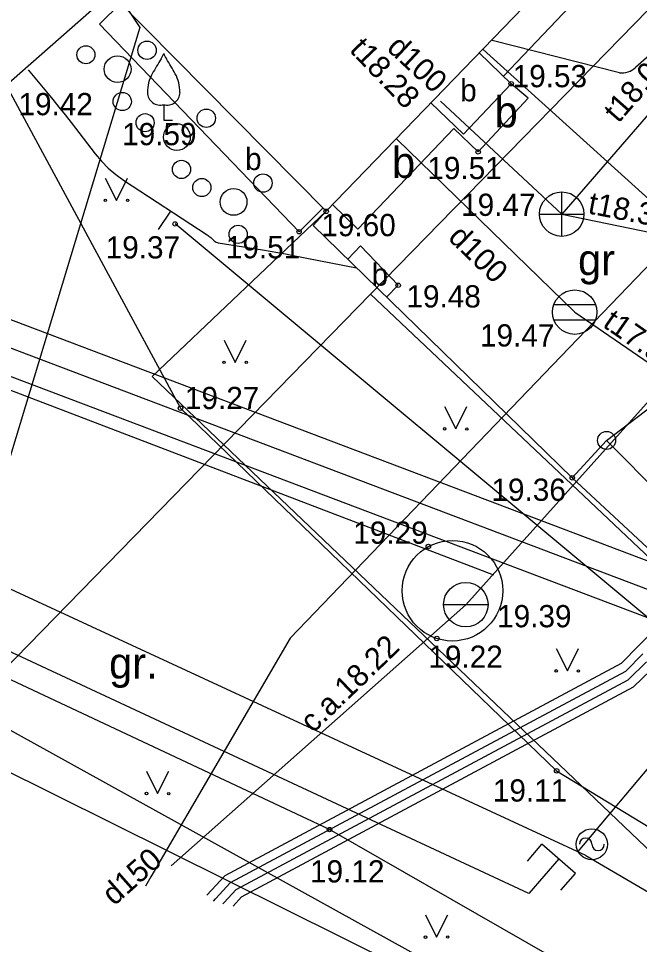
# Model space of a CAD drawing. Extents: x 532933 to 533143, y 328014 to 328163.
# Drawn here: x 532971.35 to 532985.32, y 328041.74 to 328062.57 of the extents above; entities that cross this region are included whole.
import ezdxf

# ---------------------------------------------------------------- set-up
doc = ezdxf.new("R2010")
doc.units = 0
for name, color, linetype in [('BUVE_BDET_####_####_#', 7, 'Continuous'), ('BUVE_BDET_####_TKST_#', 7, 'Continuous'), ('BUVE_EKAS_####_####_#', 7, 'Continuous'), ('CELI_CMAL_####_####_#', 7, 'Continuous'), ('CELI_CSEG_####_TKST_#', 7, 'Continuous'), ('ELEK_VADP_NEDR_####_#', 7, 'Continuous'), ('ELEK_VADP_VSPR_####_#', 7, 'Continuous'), ('ELEK_VADP_ZSPR_####_#', 7, 'Continuous'), ('GAZE_ELEM_####_####_#', 7, 'Continuous'), ('GAZE_VADP_ASP1_####_I', 7, 'Continuous'), ('GAZE_VADP_NEDR_####_#', 7, 'Continuous'), ('GAZE_VADP_ZSPD_####_#', 7, 'Continuous'), ('LKAN_ELEM_####_####_#', 7, 'Continuous'), ('LKAN_ELEM_PAST_TKST_#', 7, 'Continuous'), ('LKAN_VADP_PAST_####_#', 7, 'Continuous'), ('LKAN_VADP_PAST_TKST_#', 7, 'Continuous'), ('NORB_ELEM_####_####_#', 7, 'Continuous'), ('NORB_ZOGS_BARJ_####_#', 7, 'Continuous'), ('NORB_ZOGS_ZSTP_####_#', 7, 'Continuous'), ('RAMI_UZMR_####_####_#', 7, 'Continuous'), ('RELJ_AATZ_####_TKST_#', 7, 'Continuous'), ('RELJ_ELEM_####_####_#', 7, 'Continuous'), ('RELJ_HORZ_PAMT_####_#', 7, 'Continuous'), ('ROBZ_UZMR_####_####_#', 7, 'Continuous'), ('SAKT_VADP_KABE_####_#', 7, 'Continuous'), ('SAKT_VADV_PKAB_####_#', 7, 'Continuous'), ('SILT_VADP_UDEN_####_#', 7, 'Continuous'), ('SILT_VADP_UDEN_TKAM_#', 7, 'Continuous'), ('SKAN_ELEM_####_####_#', 7, 'Continuous'), ('SKAN_ELEM_PAST_TKST_#', 7, 'Continuous'), ('SKAN_VADP_PAST_####_#', 7, 'Continuous'), ('SKAN_VADP_PAST_TKST_#', 7, 'Continuous'), ('TERT_ELEM_####_####_#', 7, 'Continuous'), ('TERT_KRND_####_####_#', 7, 'Continuous'), ('UDTK_DETV_####_####_#', 7, 'Continuous'), ('UDTK_ELEM_####_####_#', 7, 'Continuous'), ('UDTK_ELEM_####_TKST_#', 7, 'Continuous'), ('UDTK_VADP_UDEN_####_#', 7, 'Continuous'), ('UDTK_VADP_UDEN_TKST_#', 7, 'Continuous')]:
    doc.layers.add(name, color=color, linetype=linetype)

msp = doc.modelspace()

# ---------------------------------------------------------------- linework, layer by layer
at = {"layer": 'BUVE_BDET_####_####_#'}
for p, q in [((532973.651, 328062.91), (532973.174, 328062.438)), ((532977.663, 328057.772), (532973.174, 328062.438)), ((532981.715, 328061.795), (532982.435, 328061.1)), ((532982.435, 328061.1), (532981.359, 328059.968)), ((532980.63, 328060.672), (532981.359, 328059.968)), ((532978.201, 328058.303), (532977.663, 328057.772)), ((532978.757, 328057.152), (532979.047, 328057.451)), ((532979.047, 328057.451), (532979.893, 328056.568)), ((532979.632, 328056.3), (532979.893, 328056.568))]:
    msp.add_line(p, q, dxfattribs=at)
msp.add_lwpolyline([(532973.427, 328063.138), (532969.826, 328059.969), (532963.605, 328066.425), (532962.603, 328070.346), (532963.994, 328070.869)], dxfattribs=at)
at = {"layer": 'BUVE_EKAS_####_####_#'}
for p, q in [((532991.271, 328071.691), (532978.273, 328058.231)), ((532978.273, 328058.231), (532973.38, 328063.184))]:
    msp.add_line(p, q, dxfattribs=at)
at = {"layer": 'CELI_CMAL_####_####_#'}
for p, q in [((532982.814, 328060.778), (532982.435, 328061.1)), ((532981.691, 328059.567), (532982.814, 328060.778)), ((532981.143, 328060.097), (532981.691, 328059.567)), ((532978.418, 328058.381), (532978.987, 328057.831))]:
    msp.add_line(p, q, dxfattribs=at)
for points in [[(532982.259, 328061.27), (532998.656, 328078.496)], [(533000, 328031.505), (532994.447, 328035.097), (532978.349, 328044.324), (532965.504, 328050.351), (532957.768, 328064.457), (532957.166, 328076.262)], [(532971.073, 328061.066), (532974.996, 328053.804), (532983.457, 328045.647), (532997.471, 328037.127), (533000, 328035.732)], [(532978.987, 328057.831), (532981.143, 328060.097)], [(532988.134, 328056.767), (532997.581, 328045.566), (533000.47, 328043.392), (533005, 328040.625), (533007.859, 328041.253), (533010.858, 328043.033), (533013.229, 328045.301), (533015.914, 328043.382), (533018.913, 328040.311), (533019.227, 328038.915), (533018.286, 328036.96), (533015.914, 328034.657), (533011.586, 328033.95), (533007.336, 328035.18), (533001.373, 328038.391), (532990.886, 328046.732), (532984.581, 328053.078)]]:
    msp.add_lwpolyline(points, dxfattribs=at)
at = {"layer": 'ELEK_VADP_NEDR_####_#'}
for points in [[(532975.982, 328042.686), (532976.247, 328042.975), (532985.068, 328047.695), (532985.481, 328048.096)], [(532976.179, 328042.603), (532976.372, 328042.814), (532985.188, 328047.532), (532985.571, 328047.904)]]:
    msp.add_lwpolyline(points, dxfattribs=at)
at = {"layer": 'ELEK_VADP_VSPR_####_#'}
for p, q in [((532983.183, 328054.585), (532995.463, 328067.37)), ((532995.987, 328059.254), (532985.309, 328048.465))]:
    msp.add_line(p, q, dxfattribs=at)
for points in [[(532983.183, 328054.585), (532977.465, 328048.631), (532974.331, 328043.264)], [(532975.59, 328042.849), (532975.999, 328043.294), (532984.915, 328048.066), (532985.309, 328048.464)], [(532975.786, 328042.767), (532976.124, 328043.135), (532985.01, 328047.89), (532985.395, 328048.279)], [(532974.331, 328043.264), (532974.208, 328043.054)], [(532975.737, 328042.713), (532975.785, 328042.766)], [(532975.95, 328042.651), (532975.98, 328042.684)]]:
    msp.add_lwpolyline(points, dxfattribs=at)
at = {"layer": 'ELEK_VADP_ZSPR_####_#'}
msp.add_line((532984.87, 328061.343), (532982.007, 328062.074), dxfattribs=at)
for points in [[(532994.175, 328069.331), (532985.231, 328061.466)], [(532999.357, 328047.227), (532998.507, 328046.78), (532981.807, 328061.871)]]:
    msp.add_lwpolyline(points, dxfattribs=at)
msp.add_arc((532984.901, 328061.842), 0.5, 266.4502, 311.3292, dxfattribs=at)
at = {"layer": 'GAZE_ELEM_####_####_#'}
for p, q in [((532982.799, 328043.618), (532983.127, 328043.995)), ((532983.881, 328043.339), (532983.127, 328043.995)), ((532983.553, 328042.961), (532983.881, 328043.339))]:
    msp.add_line(p, q, dxfattribs=at)
msp.add_circle((532984.249, 328043.993), 0.35, dxfattribs=at)
for centre, start, end in [((532984.109, 328043.993), 0, 180), ((532984.389, 328043.993), 180, 0)]:
    msp.add_arc(centre, 0.14, start, end, dxfattribs=at)
at = {"layer": 'GAZE_VADP_ASP1_####_I'}
for p, q in [((532984.115, 328043.743), (532946.921, 328060.941)), ((532991.712, 328053.108), (532983.933, 328043.83))]:
    msp.add_line(p, q, dxfattribs=at)
msp.add_lwpolyline([(532984.115, 328043.743), (533000, 328034.443)], dxfattribs=at)
at = {"layer": 'GAZE_VADP_NEDR_####_#'}
for p, q in [((532982.828, 328042.889), (532946.421, 328059.848)), ((532983.504, 328043.667), (532982.828, 328042.889))]:
    msp.add_line(p, q, dxfattribs=at)
at = {"layer": 'GAZE_VADP_ZSPD_####_#'}
msp.add_line((532954.128, 328054.064), (532985.007, 328038.734), dxfattribs=at)
at = {"layer": 'LKAN_ELEM_####_####_#'}
for p, q in [((532983.396, 328056.138), (532984.332, 328056.138)), ((532983.396, 328055.788), (532984.332, 328055.788))]:
    msp.add_line(p, q, dxfattribs=at)
msp.add_circle((532983.864, 328055.963), 0.5, dxfattribs=at)
at = {"layer": 'LKAN_VADP_PAST_####_#'}
for p, q in [((532979.863, 328059.851), (532983.864, 328055.963)), ((532983.864, 328055.963), (532996.624, 328047.223))]:
    msp.add_line(p, q, dxfattribs=at)
at = {"layer": 'NORB_ELEM_####_####_#'}
msp.add_circle((532984.581, 328053.078), 0.202, dxfattribs=at)
at = {"layer": 'NORB_ZOGS_BARJ_####_#'}
msp.add_line((532984.581, 328053.078), (532986.149, 328054.27), dxfattribs=at)
at = {"layer": 'NORB_ZOGS_ZSTP_####_#'}
for p, q in [((532977.979, 328057.909), (532983.808, 328052.237)), ((532983.808, 328052.237), (532984.581, 328053.078))]:
    msp.add_line(p, q, dxfattribs=at)
for points in [[(532977.979, 328057.909), (532978.273, 328058.231)], [(532983.808, 328052.237), (532997.278, 328039.721)]]:
    msp.add_lwpolyline(points, dxfattribs=at)
at = {"layer": 'RAMI_UZMR_####_####_#'}
msp.add_lwpolyline([(532947.854, 328059.458), (532970.012, 328105.269), (532980.164, 328130.66), (532983.041, 328140.509), (533003.397, 328153.917), (533034.71, 328122.623), (533045.001, 328112.629), (533020.332, 328088.009), (533039.378, 328069.977), (533029.682, 328029.753), (533016.724, 328021.343), (532947.854, 328059.458)], dxfattribs=at)
at = {"layer": 'RELJ_ELEM_####_####_#'}
for centre in [(532982.435, 328061.1), (532981.691, 328059.567), (532978.273, 328058.231), (532974.874, 328057.947), (532977.663, 328057.772), (532979.893, 328056.568), (532974.996, 328053.804), (532983.808, 328052.237), (532980.572, 328050.691), (532980.762, 328048.622), (532983.457, 328045.647), (532978.349, 328044.324)]:
    msp.add_circle(centre, 0.05, dxfattribs=at)
at = {"layer": 'RELJ_HORZ_PAMT_####_#'}
msp.add_line((532974.503, 328057.819), (532974.778, 328058.238), dxfattribs=at)
msp.add_lwpolyline([(532971.569, 328061.415), (532971.982, 328060.916), (532972.122, 328060.745), (532972.261, 328060.573), (532972.399, 328060.399), (532972.535, 328060.225), (532973.076, 328059.525), (532973.218, 328059.357), (532973.372, 328059.202), (532973.538, 328059.061), (532973.717, 328058.933), (532975.594, 328057.703), (532975.615, 328057.688), (532975.636, 328057.672), (532975.657, 328057.656), (532975.676, 328057.639), (532975.754, 328057.568), (532975.774, 328057.552), (532975.796, 328057.54), (532975.819, 328057.53), (532975.844, 328057.524), (532976.837, 328057.362), (532977.011, 328057.333), (532977.184, 328057.303), (532977.358, 328057.271), (532977.531, 328057.237), (532978.955, 328056.957)], dxfattribs=at)
at = {"layer": 'ROBZ_UZMR_####_####_#'}
for points in [[(532954.932, 328051.068), (532962.791, 328075.982), (532977.358, 328090.737), (532984.352, 328083.929), (532990.879, 328090.61), (533001.874, 328079.871), (532999.253, 328076.841), (532993.949, 328071.405), (532979.271, 328056.364), (532968.026, 328044.841)], [(532979.271, 328056.364), (532993.949, 328071.405), (533030.421, 328036.082), (533029.157, 328030.58), (533020.389, 328026.352), (532998.604, 328038.086)]]:
    msp.add_lwpolyline(points, close=True, dxfattribs=at)
msp.add_lwpolyline([(532952.676, 328043.916), (532954.932, 328051.068), (532968.026, 328044.841), (532979.271, 328056.364), (532998.604, 328038.086), (533020.389, 328026.352), (533032.36, 328019.904)], dxfattribs=at)
at = {"layer": 'SAKT_VADP_KABE_####_#'}
msp.add_lwpolyline([(532978.273, 328058.231), (532974.357, 328054.515), (532986.104, 328043.323), (532986.906, 328042.559), (532995.203, 328051.267)], dxfattribs=at)
at = {"layer": 'SAKT_VADV_PKAB_####_#'}
for p, q in [((532957.876, 328087.235), (532974.079, 328062.362)), ((532974.079, 328062.362), (532968.787, 328044.862))]:
    msp.add_line(p, q, dxfattribs=at)
at = {"layer": 'SILT_VADP_UDEN_####_#'}
msp.add_line((533000, 328044.239), (532967.835, 328056.416), dxfattribs=at)
at = {"layer": 'SILT_VADP_UDEN_TKAM_#'}
for points in [[(532986.087, 328050.147), (532968.048, 328056.976), (532958.307, 328060.714)], [(532985.663, 328049.025), (532967.621, 328055.855), (532957.878, 328059.593)]]:
    msp.add_lwpolyline(points, dxfattribs=at)
at = {"layer": 'SKAN_ELEM_####_####_#'}
for p, q in [((532983.572, 328057.668), (532983.572, 328058.668)), ((532983.072, 328058.168), (532984.072, 328058.168))]:
    msp.add_line(p, q, dxfattribs=at)
msp.add_circle((532983.572, 328058.168), 0.5, dxfattribs=at)
at = {"layer": 'SKAN_VADP_PAST_####_#'}
for points in [[(533000, 328076.986), (532997.194, 328073.892), (532983.572, 328058.168), (532980.848, 328060.709)], [(532983.572, 328058.168), (532994.423, 328055.929)]]:
    msp.add_lwpolyline(points, dxfattribs=at)
at = {"layer": 'TERT_ELEM_####_####_#'}
for p, q in [((532974.619, 328060.63), (532974.619, 328060.278)), ((532974.619, 328060.278), (532974.819, 328060.278)), ((532973.305, 328058.977), (532973.555, 328058.477)), ((532973.555, 328058.477), (532973.805, 328058.977)), ((532975.975, 328055.334), (532976.225, 328054.834)), ((532976.225, 328054.834), (532976.475, 328055.334)), ((532980.937, 328053.838), (532981.187, 328053.338)), ((532981.187, 328053.338), (532981.437, 328053.838)), ((532983.448, 328048.394), (532983.698, 328047.894)), ((532983.698, 328047.894), (532983.948, 328048.394)), ((532974.231, 328045.636), (532974.481, 328045.136)), ((532974.481, 328045.136), (532974.731, 328045.636)), ((532980.508, 328042.405), (532980.758, 328041.905)), ((532980.758, 328041.905), (532981.008, 328042.405))]:
    msp.add_line(p, q, dxfattribs=at)
for centre, radius in [((532972.868, 328061.752), 0.204), ((532974.244, 328061.853), 0.207), ((532973.582, 328061.428), 0.301), ((532973.686, 328060.7), 0.205), ((532975.576, 328060.325), 0.207), ((532974.2, 328060.224), 0.204), ((532974.915, 328059.901), 0.301), ((532975.018, 328059.173), 0.205), ((532976.851, 328058.867), 0.207), ((532975.476, 328058.766), 0.204), ((532976.19, 328058.442), 0.301), ((532973.305, 328058.477), 0.028), ((532973.805, 328058.477), 0.0263), ((532976.293, 328057.714), 0.205), ((532975.975, 328054.834), 0.028), ((532976.475, 328054.834), 0.0263), ((532980.937, 328053.338), 0.028), ((532981.437, 328053.338), 0.0263), ((532983.447, 328047.894), 0.028), ((532983.947, 328047.894), 0.0263), ((532974.231, 328045.136), 0.028), ((532974.731, 328045.136), 0.0263), ((532980.508, 328041.905), 0.028), ((532981.008, 328041.905), 0.0263)]:
    msp.add_circle(centre, radius, dxfattribs=at)
for centre, radius, start, end in [((532974.202, 328061.916), 0.439, 324.3837, 341.712), ((532975.036, 328061.916), 0.439, 198.288, 215.6163), ((532987.244, 328053.882), 14.88, 148.4844, 149.9901), ((532961.994, 328053.882), 14.88, 30.0099, 31.5156), ((532975.143, 328060.903), 0.89, 151.757, 179.9138), ((532974.094, 328060.903), 0.89, 0.0862, 28.243), ((532974.542, 328060.909), 0.29, 181.0782, 285.2823), ((532974.695, 328060.909), 0.29, 254.7177, 358.9218)]:
    msp.add_arc(centre, radius, start, end, dxfattribs=at)
at = {"layer": 'TERT_KRND_####_####_#'}
msp.add_line((532995.34, 328040.895), (532974.874, 328057.947), dxfattribs=at)
at = {"layer": 'UDTK_DETV_####_####_#'}
msp.add_circle((532981.113, 328049.697), 1.131, dxfattribs=at)
at = {"layer": 'UDTK_ELEM_####_####_#'}
msp.add_line((532980.914, 328049.384), (532981.914, 328049.384), dxfattribs=at)
msp.add_circle((532981.414, 328049.384), 0.5, dxfattribs=at)
at = {"layer": 'UDTK_VADP_UDEN_####_#'}
msp.add_line((532982.048, 328050.046), (532947.902, 328063.085), dxfattribs=at)
msp.add_lwpolyline([(532996.68, 328066.401), (532981.413, 328049.383), (532974.784, 328043.51)], dxfattribs=at)

# ---------------------------------------------------------------- texts
at = {"layer": 'BUVE_BDET_####_TKST_#'}
for p in [(532981.102, 328060.705), (532976.264, 328059.159), (532979.109, 328056.56)]:
    msp.add_text(' b', height=0.5, dxfattribs=at).set_placement(p)
at = {"layer": 'CELI_CSEG_####_TKST_#'}
for s, p in [(' b', (532981.802, 328060.12)), (' b', (532979.494, 328058.981)), ('gr', (532983.939, 328056.793)), ('gr.', (532973.39, 328047.72))]:
    msp.add_text(s, height=0.7, dxfattribs=at).set_placement(p)
at = {"layer": 'LKAN_ELEM_PAST_TKST_#'}
msp.add_text(' 19.47', height=0.5, dxfattribs=at).set_placement((532981.547, 328055.19))
at = {"layer": 'LKAN_VADP_PAST_TKST_#'}
for s, rotation, p in [('d100', 315.8207, (532980.992, 328057.615)), ('t17.98', 325.1225, (532984.468, 328055.651))]:
    msp.add_text(s, height=0.5, rotation=rotation, dxfattribs=at).set_placement(p)
at = {"layer": 'RELJ_AATZ_####_TKST_#'}
for s, p in [(' 19.53', (532982.282, 328061.022)), (' 19.42', (532971.166, 328060.392)), (' 19.59', (532973.499, 328059.718)), (' 19.51', (532980.363, 328058.955)), (' 19.60', (532977.979, 328057.671)), (' 19.37', (532973.127, 328057.17)), (' 19.51', (532975.831, 328057.174)), (' 19.48', (532979.893, 328056.068)), (' 19.27', (532974.91, 328053.782)), (' 19.36', (532981.805, 328051.719)), (' 19.29', (532978.697, 328050.754)), (' 19.22', (532980.386, 328047.963)), (' 19.11', (532981.837, 328044.955)), (' 19.12', (532977.724, 328043.135))]:
    msp.add_text(s, height=0.5, dxfattribs=at).set_placement(p)
at = {"layer": 'SKAN_ELEM_PAST_TKST_#'}
msp.add_text(' 19.47', height=0.5, dxfattribs=at).set_placement((532981.123, 328058.128))
at = {"layer": 'SKAN_VADP_PAST_TKST_#'}
for s, rotation, p in [('d100', 316.9892, (532979.612, 328061.876)), ('t18.28', 313.6864, (532978.776, 328061.847)), ('t18.09', 48.7139, (532984.846, 328060.196)), ('t18.35', 349.0523, (532984.143, 328058.185))]:
    msp.add_text(s, height=0.5, rotation=rotation, dxfattribs=at).set_placement(p)
at = {"layer": 'UDTK_ELEM_####_TKST_#'}
msp.add_text(' 19.39', height=0.5, dxfattribs=at).set_placement((532981.933, 328048.875))
at = {"layer": 'UDTK_VADP_UDEN_TKST_#'}
for s, rotation, p in [('c.a.18.22', 43.9576, (532977.979, 328046.48)), ('d150', 41.4356, (532973.503, 328042.595))]:
    msp.add_text(s, height=0.5, rotation=rotation, dxfattribs=at).set_placement(p)

doc.saveas('drawing.dxf')
